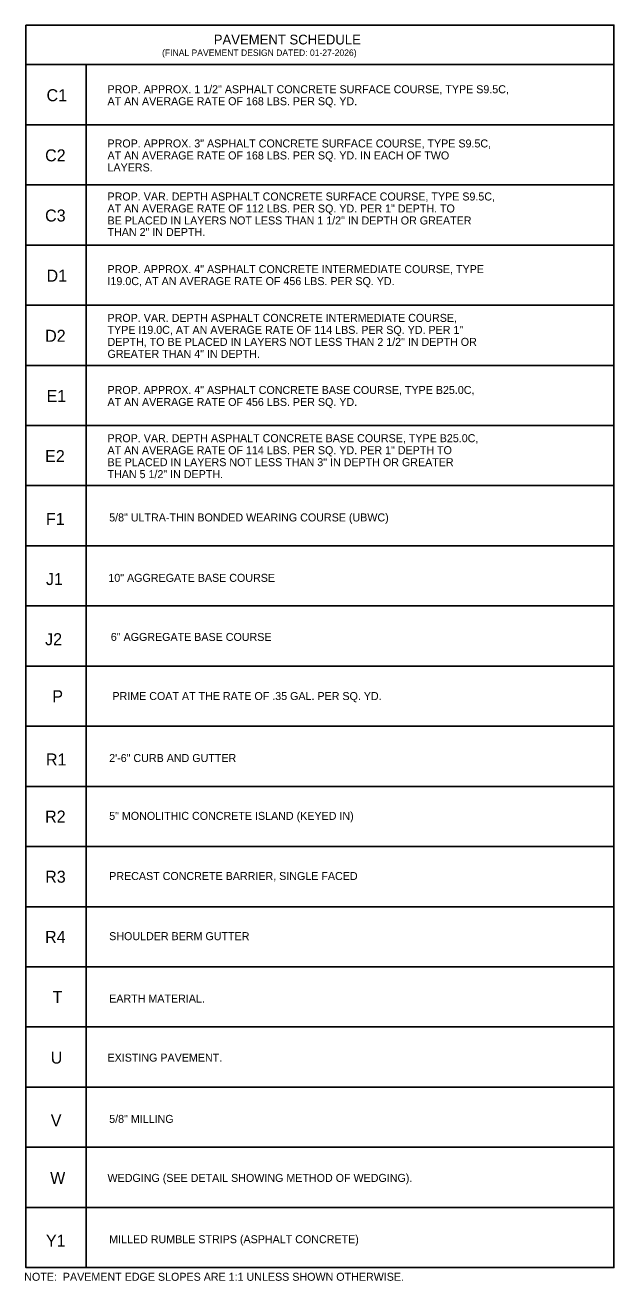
# Model space of a CAD drawing. Extents: x 1901582 to 1902252, y 193723 to 194156.
# Drawn here: x 1901983 to 1902021.4, y 194073.8 to 194155.8 of the extents above; entities that cross this region are included whole.
import ezdxf

# ---------------------------------------------------------------- set-up
doc = ezdxf.new("R2010")
doc.units = 0
for name, color, linetype in [('Old_Level_19', 7, 'Continuous'), ('Old_Level_21', 7, 'Continuous'), ('Prop Pavement Schedule Description CELL', 7, 'Continuous')]:
    doc.layers.add(name, color=color, linetype=linetype)

msp = doc.modelspace()

# ---------------------------------------------------------------- linework, layer by layer
at = {"layer": 'Old_Level_19'}
msp.add_lwpolyline([(1901983.033, 194155.83), (1902021.434, 194155.83), (1902021.434, 194153.252), (1901983.033, 194153.252)], close=True, dxfattribs=at)
for points in [[(1901986.96, 194149.325), (1901983.033, 194149.325), (1901983.033, 194153.252), (1902021.433, 194153.252), (1902021.433, 194149.325), (1901986.96, 194149.325), (1901986.96, 194153.252)], [(1901986.96, 194145.398), (1901983.033, 194145.398), (1901983.033, 194149.325), (1902021.433, 194149.325), (1902021.433, 194145.398), (1901986.96, 194145.398), (1901986.96, 194149.325)], [(1901986.96, 194141.47), (1901983.033, 194141.47), (1901983.033, 194145.398), (1902021.433, 194145.398), (1902021.433, 194141.47), (1901986.96, 194141.47), (1901986.96, 194145.398)], [(1901986.96, 194137.543), (1901983.033, 194137.543), (1901983.033, 194141.47), (1902021.433, 194141.47), (1902021.433, 194137.543), (1901986.96, 194137.543), (1901986.96, 194141.47)], [(1901986.96, 194133.616), (1901983.033, 194133.616), (1901983.033, 194137.543), (1902021.433, 194137.543), (1902021.433, 194133.616), (1901986.96, 194133.616), (1901986.96, 194137.543)], [(1901986.96, 194129.689), (1901983.033, 194129.689), (1901983.033, 194133.616), (1902021.433, 194133.616), (1902021.433, 194129.689), (1901986.96, 194129.689), (1901986.96, 194133.616)], [(1901986.96, 194125.762), (1901983.033, 194125.762), (1901983.033, 194129.689), (1902021.433, 194129.689), (1902021.433, 194125.762), (1901986.96, 194125.762), (1901986.96, 194129.689)], [(1901986.96, 194121.834), (1901983.033, 194121.834), (1901983.033, 194125.762), (1902021.433, 194125.762), (1902021.433, 194121.834), (1901986.96, 194121.834), (1901986.96, 194125.762)], [(1901986.96, 194117.907), (1901983.033, 194117.907), (1901983.033, 194121.834), (1902021.433, 194121.834), (1902021.433, 194117.907), (1901986.96, 194117.907), (1901986.96, 194121.834)], [(1901986.96, 194113.98), (1901983.033, 194113.98), (1901983.033, 194117.907), (1902021.433, 194117.907), (1902021.433, 194113.98), (1901986.96, 194113.98), (1901986.96, 194117.907)], [(1901986.96, 194110.053), (1901983.033, 194110.053), (1901983.033, 194113.98), (1902021.433, 194113.98), (1902021.433, 194110.053), (1901986.96, 194110.053), (1901986.96, 194113.98)], [(1901986.96, 194106.126), (1901983.033, 194106.126), (1901983.033, 194110.053), (1902021.433, 194110.053), (1902021.433, 194106.126), (1901986.96, 194106.126), (1901986.96, 194110.053)], [(1901986.96, 194102.198), (1901983.033, 194102.198), (1901983.033, 194106.126), (1902021.433, 194106.126), (1902021.433, 194102.198), (1901986.96, 194102.198), (1901986.96, 194106.126)], [(1901986.96, 194098.271), (1901983.033, 194098.271), (1901983.033, 194102.198), (1902021.433, 194102.198), (1902021.433, 194098.271), (1901986.96, 194098.271), (1901986.96, 194102.198)], [(1901986.96, 194094.344), (1901983.033, 194094.344), (1901983.033, 194098.271), (1902021.433, 194098.271), (1902021.433, 194094.344), (1901986.96, 194094.344), (1901986.96, 194098.271)], [(1901986.96, 194090.417), (1901983.033, 194090.417), (1901983.033, 194094.344), (1902021.433, 194094.344), (1902021.433, 194090.417), (1901986.96, 194090.417), (1901986.96, 194094.344)], [(1901986.96, 194086.49), (1901983.033, 194086.49), (1901983.033, 194090.417), (1902021.433, 194090.417), (1902021.433, 194086.49), (1901986.96, 194086.49), (1901986.96, 194090.417)], [(1901986.96, 194082.562), (1901983.033, 194082.562), (1901983.033, 194086.49), (1902021.433, 194086.49), (1902021.433, 194082.562), (1901986.96, 194082.562), (1901986.96, 194086.49)], [(1901986.96, 194078.635), (1901983.033, 194078.635), (1901983.033, 194082.562), (1902021.433, 194082.562), (1902021.433, 194078.635), (1901986.96, 194078.635), (1901986.96, 194082.562)], [(1901986.96, 194074.708), (1901983.033, 194074.708), (1901983.033, 194078.635), (1902021.433, 194078.635), (1902021.433, 194074.708), (1901986.96, 194074.708), (1901986.96, 194078.635)]]:
    msp.add_lwpolyline(points, dxfattribs=at)

# ---------------------------------------------------------------- texts
at = {"layer": 'Old_Level_21'}
for s, height, p in [('PAVEMENT SCHEDULE', 0.64, (1901995.3, 194154.566)), ('(FINAL PAVEMENT DESIGN DATED: 01-27-2026)', 0.41792, (1901991.925, 194153.821)), ('C1', 0.784, (1901984.379, 194150.861)), ('PROP. APPROX. 1 1/2" ASPHALT CONCRETE SURFACE COURSE, TYPE S9.5C,', 0.5224, (1901988.36, 194151.381)), ('AT AN AVERAGE RATE OF 168 LBS. PER SQ. YD.', 0.5224, (1901988.36, 194150.598)), ('PROP. APPROX. 3" ASPHALT CONCRETE SURFACE COURSE, TYPE S9.5C,', 0.5224, (1901988.36, 194147.842)), ('C2', 0.784, (1901984.285, 194146.934)), ('AT AN AVERAGE RATE OF 168 LBS. PER SQ. YD. IN EACH OF TWO', 0.5224, (1901988.36, 194147.059)), ('LAYERS.', 0.5224, (1901988.36, 194146.276)), ('PROP. VAR. DEPTH ASPHALT CONCRETE SURFACE COURSE, TYPE S9.5C,', 0.5224, (1901988.36, 194144.379)), ('AT AN AVERAGE RATE OF 112 LBS. PER SQ. YD. PER 1" DEPTH. TO', 0.5224, (1901988.36, 194143.596)), ('C3', 0.784, (1901984.285, 194143.006)), ('BE PLACED IN LAYERS NOT LESS THAN 1 1/2" IN DEPTH OR GREATER', 0.5224, (1901988.36, 194142.813)), ('THAN 2" IN DEPTH.', 0.5224, (1901988.36, 194142.059)), ('PROP. APPROX. 4" ASPHALT CONCRETE INTERMEDIATE COURSE, TYPE', 0.5224, (1901988.36, 194139.637)), ('D1', 0.784, (1901984.379, 194139.079)), ('I19.0C, AT AN AVERAGE RATE OF 456 LBS. PER SQ. YD.', 0.5224, (1901988.36, 194138.854)), ('PROP. VAR. DEPTH ASPHALT CONCRETE INTERMEDIATE COURSE,', 0.5224, (1901988.36, 194136.453)), ('D2', 0.784, (1901984.285, 194135.152)), ('TYPE I19.0C, AT AN AVERAGE RATE OF 114 LBS. PER SQ. YD. PER 1" ', 0.5224, (1901988.36, 194135.67)), ('DEPTH, TO BE PLACED IN LAYERS NOT LESS THAN 2 1/2" IN DEPTH OR', 0.5224, (1901988.36, 194134.886)), ('GREATER THAN 4" IN DEPTH.', 0.5224, (1901988.36, 194134.103)), ('E1', 0.784, (1901984.379, 194131.224)), ('PROP. APPROX. 4" ASPHALT CONCRETE BASE COURSE, TYPE B25.0C,', 0.5224, (1901988.36, 194131.746)), ('AT AN AVERAGE RATE OF 456 LBS. PER SQ. YD.', 0.5224, (1901988.36, 194130.962)), ('PROP. VAR. DEPTH ASPHALT CONCRETE BASE COURSE, TYPE B25.0C,', 0.5224, (1901988.36, 194128.598)), ('E2', 0.784, (1901984.285, 194127.297)), ('AT AN AVERAGE RATE OF 114 LBS. PER SQ. YD. PER 1" DEPTH TO', 0.5224, (1901988.36, 194127.815)), ('THAN 5 1/2" IN DEPTH.', 0.5224, (1901988.36, 194126.249)), ('BE PLACED IN LAYERS NOT LESS THAN 3" IN DEPTH OR GREATER', 0.5224, (1901988.36, 194127.032)), ('F1', 0.784, (1901984.341, 194123.199)), ('5/8" ULTRA-THIN BONDED WEARING COURSE (UBWC)', 0.5224, (1901988.47, 194123.424)), ('J1', 0.784, (1901984.341, 194119.271)), ('10" AGGREGATE BASE COURSE', 0.5224, (1901988.416, 194119.48)), ('J2', 0.784, (1901984.285, 194115.344)), ('6" AGGREGATE BASE COURSE', 0.5224, (1901988.577, 194115.621)), ('P', 0.784, (1901984.756, 194111.617)), ('R1', 0.784, (1901984.341, 194107.49)), ('2\'-6" CURB AND GUTTER', 0.5224, (1901988.47, 194107.715)), ('R2', 0.784, (1901984.285, 194103.763)), ('5" MONOLITHIC CONCRETE ISLAND (KEYED IN)', 0.5224, (1901988.47, 194103.938)), ('R3', 0.784, (1901984.29, 194099.836)), ('PRECAST CONCRETE BARRIER, SINGLE FACED', 0.5224, (1901988.47, 194100.011)), ('R4', 0.784, (1901984.282, 194095.908)), ('SHOULDER BERM GUTTER', 0.5224, (1901988.47, 194096.084)), ('T', 0.784, (1901984.772, 194091.981)), ('EARTH MATERIAL.', 0.5224, (1901988.47, 194092.009)), ('U', 0.784, (1901984.654, 194088.026)), ('EXISTING PAVEMENT.', 0.5224, (1901988.36, 194088.154)), ('V', 0.784, (1901984.655, 194083.927)), ('5/8" MILLING', 0.5224, (1901988.47, 194084.152)), ('W', 0.784, (1901984.614, 194080.171)), ('WEDGING (SEE DETAIL SHOWING METHOD OF WEDGING).', 0.5224, (1901988.36, 194080.3)), ('Y1', 0.784, (1901984.341, 194076.072)), ('MILLED RUMBLE STRIPS (ASPHALT CONCRETE)', 0.5224, (1901988.47, 194076.297)), ('NOTE:  PAVEMENT EDGE SLOPES ARE 1:1 UNLESS SHOWN OTHERWISE.', 0.5224, (1901982.921, 194073.845))]:
    msp.add_text(s, height=height, dxfattribs=at).set_placement(p)
at = {"layer": 'Prop Pavement Schedule Description CELL'}
msp.add_text('PRIME COAT AT THE RATE OF .35 GAL. PER SQ. YD.', height=0.5224, dxfattribs=at).set_placement((1901988.681, 194111.762))

doc.saveas('drawing.dxf')
